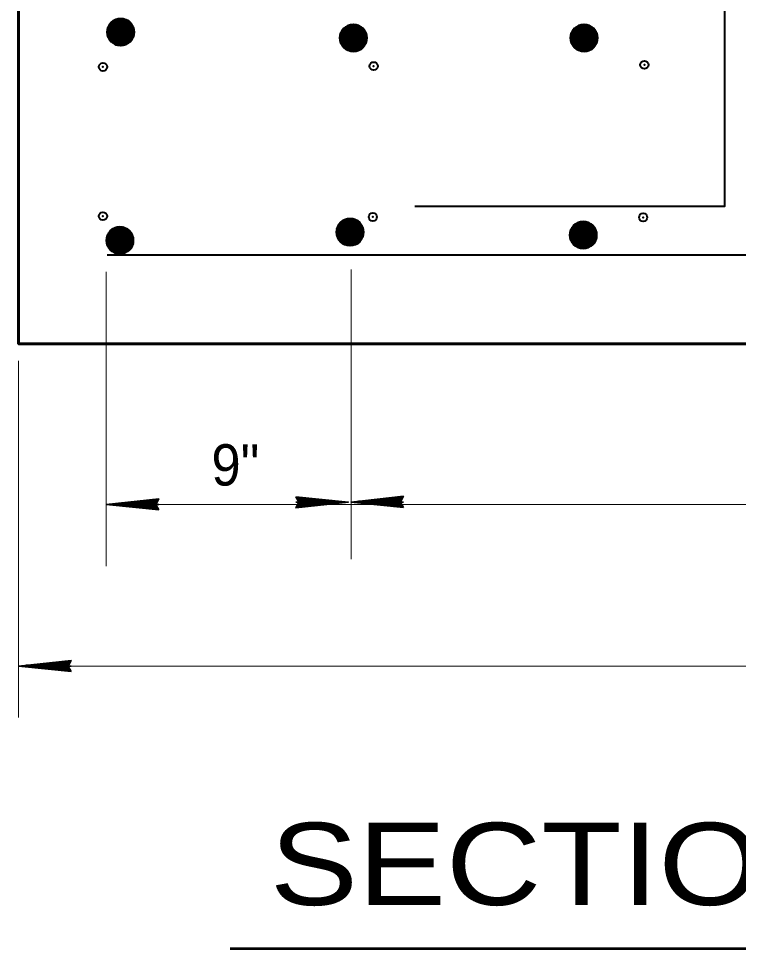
# Model space of a CAD drawing. Extents: x 14.14 to 17.34, y -1.61 to 0.38.
# Drawn here: x 15.6814 to 15.8265, y -0.6192 to -0.4318 of the extents above; entities that cross this region are included whole.
import ezdxf
from ezdxf.enums import TextEntityAlignment as Align

# ---------------------------------------------------------------- set-up
doc = ezdxf.new("R2010")
doc.units = 0
doc.header["$LTSCALE"] = 0.0033
doc.header["$PDMODE"] = 32
doc.header["$PDSIZE"] = 0.00165
doc.layers.add('1', color=7, linetype='Continuous', lineweight=40)

msp = doc.modelspace()

# ---------------------------------------------------------------- linework, layer by layer
at = {"layer": '1'}
for p, q in [((15.699917, -0.432917), (15.7045, -0.435083)), ((15.70025, -0.432917), (15.704167, -0.433583)), ((15.70025, -0.433083), (15.704167, -0.433833)), ((15.700333, -0.432583), (15.704167, -0.43325)), ((15.70225, -0.433417), (15.703583, -0.432417)), ((15.704333, -0.43325), (15.703083, -0.432083)), ((15.699917, -0.43475), (15.703833, -0.4355)), ((15.7, -0.434333), (15.703833, -0.435083)), ((15.7, -0.4345), (15.703833, -0.43525)), ((15.700083, -0.433917), (15.703917, -0.434583)), ((15.700083, -0.434083), (15.703917, -0.434833)), ((15.700167, -0.433333), (15.704083, -0.434083)), ((15.700167, -0.4335), (15.704083, -0.43425)), ((15.700167, -0.43375), (15.704, -0.4345)), ((15.746833, -0.434083), (15.751417, -0.43625)), ((15.747083, -0.4345), (15.751, -0.43525)), ((15.747083, -0.434667), (15.751, -0.435417)), ((15.747083, -0.434917), (15.750917, -0.435667)), ((15.747167, -0.434083), (15.751083, -0.43475)), ((15.747167, -0.43425), (15.751083, -0.435)), ((15.74725, -0.43375), (15.751083, -0.434417)), ((15.749167, -0.434583), (15.7505, -0.433583)), ((15.75125, -0.434417), (15.75, -0.43325)), ((15.793333, -0.434083), (15.797917, -0.43625)), ((15.793583, -0.4345), (15.7975, -0.43525)), ((15.793583, -0.434667), (15.7975, -0.435417)), ((15.793583, -0.434917), (15.797417, -0.435667)), ((15.793667, -0.434083), (15.797583, -0.43475)), ((15.793667, -0.43425), (15.797583, -0.435)), ((15.79375, -0.43375), (15.797583, -0.434417)), ((15.795667, -0.434583), (15.797, -0.433583)), ((15.79775, -0.434417), (15.7965, -0.43325)), ((15.69975, -0.435667), (15.703583, -0.436417)), ((15.69975, -0.435833), (15.703583, -0.436583)), ((15.699833, -0.435167), (15.70375, -0.435917)), ((15.699833, -0.435333), (15.703667, -0.436083)), ((15.699833, -0.435583), (15.703667, -0.43625)), ((15.704083, -0.436083), (15.700333, -0.4365)), ((15.746667, -0.436833), (15.7505, -0.437583)), ((15.74675, -0.436333), (15.750667, -0.437083)), ((15.74675, -0.4365), (15.750583, -0.43725)), ((15.74675, -0.43675), (15.750583, -0.437417)), ((15.746833, -0.435917), (15.75075, -0.436667)), ((15.746917, -0.4355), (15.75075, -0.43625)), ((15.746917, -0.435667), (15.75075, -0.436417)), ((15.747, -0.435083), (15.750833, -0.43575)), ((15.747, -0.43525), (15.750833, -0.436)), ((15.793167, -0.436833), (15.797, -0.437583)), ((15.79325, -0.436333), (15.797167, -0.437083)), ((15.79325, -0.4365), (15.797083, -0.43725)), ((15.79325, -0.43675), (15.797083, -0.437417)), ((15.793333, -0.435917), (15.79725, -0.436667)), ((15.793417, -0.4355), (15.79725, -0.43625)), ((15.793417, -0.435667), (15.79725, -0.436417)), ((15.7935, -0.435083), (15.797333, -0.43575)), ((15.7935, -0.43525), (15.797333, -0.436)), ((15.746667, -0.437), (15.7505, -0.43775)), ((15.751, -0.43725), (15.74725, -0.437667)), ((15.793167, -0.437), (15.797, -0.43775)), ((15.7975, -0.43725), (15.79375, -0.437667)), ((15.750583, -0.473583), (15.749333, -0.472417)), ((15.704167, -0.47525), (15.702917, -0.474083)), ((15.746167, -0.47325), (15.75075, -0.475417)), ((15.746333, -0.47425), (15.750167, -0.474917)), ((15.746417, -0.473667), (15.750333, -0.474417)), ((15.746417, -0.473833), (15.750333, -0.474583)), ((15.746417, -0.474083), (15.75025, -0.474833)), ((15.7465, -0.47325), (15.750417, -0.473917)), ((15.7465, -0.473417), (15.750417, -0.474167)), ((15.746583, -0.472917), (15.750417, -0.473583)), ((15.7485, -0.47375), (15.749833, -0.47275)), ((15.793167, -0.473833), (15.79775, -0.476)), ((15.793417, -0.47425), (15.797333, -0.475)), ((15.7935, -0.473833), (15.797417, -0.4745)), ((15.7935, -0.474), (15.797417, -0.47475)), ((15.793583, -0.4735), (15.797417, -0.474167)), ((15.7955, -0.474333), (15.796833, -0.473333)), ((15.797583, -0.474167), (15.796333, -0.473)), ((15.69975, -0.474917), (15.704333, -0.477083)), ((15.699917, -0.475917), (15.70375, -0.476583)), ((15.699917, -0.476083), (15.70375, -0.476833)), ((15.7, -0.475333), (15.703917, -0.476083)), ((15.7, -0.4755), (15.703917, -0.47625)), ((15.7, -0.47575), (15.703833, -0.4765)), ((15.700083, -0.474917), (15.704, -0.475583)), ((15.700083, -0.475083), (15.704, -0.475833)), ((15.700167, -0.474583), (15.704, -0.47525)), ((15.702083, -0.475417), (15.703417, -0.474417)), ((15.746, -0.476), (15.749833, -0.47675)), ((15.746, -0.476167), (15.749833, -0.476917)), ((15.746083, -0.4755), (15.75, -0.47625)), ((15.746083, -0.475667), (15.749917, -0.476417)), ((15.746083, -0.475917), (15.749917, -0.476583)), ((15.746167, -0.475083), (15.750083, -0.475833)), ((15.74625, -0.474667), (15.750083, -0.475417)), ((15.74625, -0.474833), (15.750083, -0.475583)), ((15.746333, -0.474417), (15.750167, -0.475167)), ((15.793083, -0.476083), (15.797, -0.476833)), ((15.793167, -0.475667), (15.797083, -0.476417)), ((15.79325, -0.47525), (15.797083, -0.476)), ((15.79325, -0.475417), (15.797083, -0.476167)), ((15.793333, -0.474833), (15.797167, -0.4755)), ((15.793333, -0.475), (15.797167, -0.47575)), ((15.793417, -0.474417), (15.797333, -0.475167)), ((15.793417, -0.474667), (15.79725, -0.475417)), ((15.699583, -0.477667), (15.703417, -0.478417)), ((15.699583, -0.477833), (15.703417, -0.478583)), ((15.699667, -0.477167), (15.703583, -0.477917)), ((15.699667, -0.477333), (15.7035, -0.478083)), ((15.699667, -0.477583), (15.7035, -0.47825)), ((15.69975, -0.47675), (15.703667, -0.4775)), ((15.699833, -0.476333), (15.703667, -0.477083)), ((15.699833, -0.4765), (15.703667, -0.47725)), ((15.703917, -0.478083), (15.700167, -0.4785)), ((15.750333, -0.476417), (15.746583, -0.476833)), ((15.793, -0.476583), (15.796833, -0.477333)), ((15.793, -0.47675), (15.796833, -0.4775)), ((15.793083, -0.47625), (15.796917, -0.477)), ((15.793083, -0.4765), (15.796917, -0.477167)), ((15.797333, -0.477), (15.793583, -0.477417)), ((15.69925, -0.479417), (16.07975, -0.479417))]:
    msp.add_line(p, q, dxfattribs=at)
at = {"layer": '1', "lineweight": 60}
for p, q in [((15.700167, -0.432917), (15.7, -0.435833)), ((15.700417, -0.432917), (15.700167, -0.435833)), ((15.700583, -0.432917), (15.700417, -0.435917)), ((15.70075, -0.432917), (15.7005, -0.435917)), ((15.700917, -0.432917), (15.70075, -0.435917)), ((15.701167, -0.432917), (15.701, -0.435917)), ((15.701417, -0.432917), (15.701167, -0.435917)), ((15.7015, -0.433), (15.701333, -0.435917)), ((15.701667, -0.433), (15.7015, -0.435917)), ((15.701833, -0.433), (15.701667, -0.435917)), ((15.702083, -0.433), (15.701833, -0.435917)), ((15.70225, -0.433), (15.702083, -0.435917)), ((15.7025, -0.433083), (15.70225, -0.436)), ((15.70275, -0.433083), (15.7025, -0.436)), ((15.702917, -0.433083), (15.70275, -0.436)), ((15.703, -0.433083), (15.702833, -0.436)), ((15.703167, -0.433083), (15.703, -0.436)), ((15.70325, -0.433083), (15.703083, -0.436)), ((15.7035, -0.433167), (15.70325, -0.436083)), ((15.703667, -0.433167), (15.7035, -0.436083)), ((15.703833, -0.433167), (15.703583, -0.436083)), ((15.704, -0.433167), (15.703833, -0.436083)), ((15.70425, -0.433167), (15.704083, -0.436083)), ((15.7045, -0.435083), (15.704333, -0.43325)), ((15.747083, -0.434083), (15.746917, -0.437)), ((15.747333, -0.434083), (15.747083, -0.437)), ((15.7475, -0.434083), (15.747333, -0.437083)), ((15.747667, -0.434083), (15.747417, -0.437083)), ((15.747833, -0.434083), (15.747667, -0.437083)), ((15.748083, -0.434083), (15.747917, -0.437083)), ((15.748333, -0.434083), (15.748083, -0.437083)), ((15.748417, -0.434167), (15.74825, -0.437083)), ((15.748583, -0.434167), (15.748417, -0.437083)), ((15.74875, -0.434167), (15.748583, -0.437083)), ((15.749, -0.434167), (15.74875, -0.437083)), ((15.749167, -0.434167), (15.749, -0.437083)), ((15.749417, -0.43425), (15.749167, -0.437167)), ((15.749667, -0.43425), (15.749417, -0.437167)), ((15.749833, -0.43425), (15.749667, -0.437167)), ((15.749917, -0.43425), (15.74975, -0.437167)), ((15.750083, -0.43425), (15.749917, -0.437167)), ((15.750167, -0.43425), (15.75, -0.437167)), ((15.750417, -0.434333), (15.750167, -0.43725)), ((15.750583, -0.434333), (15.750417, -0.43725)), ((15.75075, -0.434333), (15.7505, -0.43725)), ((15.750917, -0.434333), (15.75075, -0.43725)), ((15.751167, -0.434333), (15.751, -0.43725)), ((15.751417, -0.43625), (15.75125, -0.434417)), ((15.793583, -0.434083), (15.793417, -0.437)), ((15.793833, -0.434083), (15.793583, -0.437)), ((15.794, -0.434083), (15.793833, -0.437083)), ((15.794167, -0.434083), (15.793917, -0.437083)), ((15.794333, -0.434083), (15.794167, -0.437083)), ((15.794583, -0.434083), (15.794417, -0.437083)), ((15.794833, -0.434083), (15.794583, -0.437083)), ((15.794917, -0.434167), (15.79475, -0.437083)), ((15.795083, -0.434167), (15.794917, -0.437083)), ((15.79525, -0.434167), (15.795083, -0.437083)), ((15.7955, -0.434167), (15.79525, -0.437083)), ((15.795667, -0.434167), (15.7955, -0.437083)), ((15.795917, -0.43425), (15.795667, -0.437167)), ((15.796167, -0.43425), (15.795917, -0.437167)), ((15.796333, -0.43425), (15.796167, -0.437167)), ((15.796417, -0.43425), (15.79625, -0.437167)), ((15.796583, -0.43425), (15.796417, -0.437167)), ((15.796667, -0.43425), (15.7965, -0.437167)), ((15.796917, -0.434333), (15.796667, -0.43725)), ((15.797083, -0.434333), (15.796917, -0.43725)), ((15.79725, -0.434333), (15.797, -0.43725)), ((15.797417, -0.434333), (15.79725, -0.43725)), ((15.797667, -0.434333), (15.7975, -0.43725)), ((15.797917, -0.43625), (15.79775, -0.434417)), ((15.7045, -0.435083), (15.69975, -0.435833)), ((15.751417, -0.43625), (15.746667, -0.437)), ((15.797917, -0.43625), (15.793167, -0.437)), ((15.746417, -0.47325), (15.74625, -0.476167)), ((15.746667, -0.47325), (15.746417, -0.476167)), ((15.746833, -0.47325), (15.746667, -0.47625)), ((15.747, -0.47325), (15.74675, -0.47625)), ((15.747167, -0.47325), (15.747, -0.47625)), ((15.747417, -0.47325), (15.74725, -0.47625)), ((15.747667, -0.47325), (15.747417, -0.47625)), ((15.74775, -0.473333), (15.747583, -0.47625)), ((15.747917, -0.473333), (15.74775, -0.47625)), ((15.748083, -0.473333), (15.747917, -0.47625)), ((15.748333, -0.473333), (15.748083, -0.47625)), ((15.7485, -0.473333), (15.748333, -0.47625)), ((15.74875, -0.473417), (15.7485, -0.476333)), ((15.749, -0.473417), (15.74875, -0.476333)), ((15.749167, -0.473417), (15.749, -0.476333)), ((15.74925, -0.473417), (15.749083, -0.476333)), ((15.749417, -0.473417), (15.74925, -0.476333)), ((15.7495, -0.473417), (15.749333, -0.476333)), ((15.74975, -0.4735), (15.7495, -0.476417)), ((15.749917, -0.4735), (15.74975, -0.476417)), ((15.750083, -0.4735), (15.749833, -0.476417)), ((15.75025, -0.4735), (15.750083, -0.476417)), ((15.7505, -0.4735), (15.750333, -0.476417)), ((15.75075, -0.475417), (15.750583, -0.473583)), ((15.793417, -0.473833), (15.79325, -0.47675)), ((15.793667, -0.473833), (15.793417, -0.47675)), ((15.793833, -0.473833), (15.793667, -0.476833)), ((15.794, -0.473833), (15.79375, -0.476833)), ((15.794167, -0.473833), (15.794, -0.476833)), ((15.794417, -0.473833), (15.79425, -0.476833)), ((15.794667, -0.473833), (15.794417, -0.476833)), ((15.79475, -0.473917), (15.794583, -0.476833)), ((15.794917, -0.473917), (15.79475, -0.476833)), ((15.795083, -0.473917), (15.794917, -0.476833)), ((15.795333, -0.473917), (15.795083, -0.476833)), ((15.7955, -0.473917), (15.795333, -0.476833)), ((15.79575, -0.474), (15.7955, -0.476917)), ((15.796, -0.474), (15.79575, -0.476917)), ((15.796167, -0.474), (15.796, -0.476917)), ((15.79625, -0.474), (15.796083, -0.476917)), ((15.796417, -0.474), (15.79625, -0.476917)), ((15.7965, -0.474), (15.796333, -0.476917)), ((15.79675, -0.474083), (15.7965, -0.477)), ((15.796917, -0.474083), (15.79675, -0.477)), ((15.797083, -0.474083), (15.796833, -0.477)), ((15.79725, -0.474083), (15.797083, -0.477)), ((15.7975, -0.474083), (15.797333, -0.477)), ((15.79775, -0.476), (15.797583, -0.474167)), ((15.7, -0.474917), (15.699833, -0.477833)), ((15.70025, -0.474917), (15.7, -0.477833)), ((15.700417, -0.474917), (15.70025, -0.477917)), ((15.700583, -0.474917), (15.700333, -0.477917)), ((15.70075, -0.474917), (15.700583, -0.477917)), ((15.701, -0.474917), (15.700833, -0.477917)), ((15.70125, -0.474917), (15.701, -0.477917)), ((15.701333, -0.475), (15.701167, -0.477917)), ((15.7015, -0.475), (15.701333, -0.477917)), ((15.701667, -0.475), (15.7015, -0.477917)), ((15.701917, -0.475), (15.701667, -0.477917)), ((15.702083, -0.475), (15.701917, -0.477917)), ((15.702333, -0.475083), (15.702083, -0.478)), ((15.702583, -0.475083), (15.702333, -0.478)), ((15.70275, -0.475083), (15.702583, -0.478)), ((15.702833, -0.475083), (15.702667, -0.478)), ((15.703, -0.475083), (15.702833, -0.478)), ((15.703083, -0.475083), (15.702917, -0.478)), ((15.703333, -0.475167), (15.703083, -0.478083)), ((15.7035, -0.475167), (15.703333, -0.478083)), ((15.703667, -0.475167), (15.703417, -0.478083)), ((15.703833, -0.475167), (15.703667, -0.478083)), ((15.704083, -0.475167), (15.703917, -0.478083)), ((15.704333, -0.477083), (15.704167, -0.47525)), ((15.75075, -0.475417), (15.746, -0.476167)), ((15.79775, -0.476), (15.793, -0.47675)), ((15.704333, -0.477083), (15.699583, -0.477833))]:
    msp.add_line(p, q, dxfattribs=at)
at = {"layer": '1', "lineweight": 13}
for p, q in [((15.699083, -0.482833), (15.699083, -0.542167)), ((15.7485, -0.482333), (15.7485, -0.54075)), ((15.681417, -0.50075), (15.681417, -0.572667)), ((15.699083, -0.52975), (16.080083, -0.52975)), ((15.681417, -0.562333), (16.09775, -0.562333))]:
    msp.add_line(p, q, dxfattribs=at)
at = {"layer": '1', "lineweight": 35}
for p, q in [((15.709417, -0.528667), (15.702083, -0.5295)), ((15.737583, -0.52825), (15.745417, -0.529167)), ((15.737583, -0.52825), (15.745417, -0.529167)), ((15.737583, -0.528333), (15.745417, -0.529167)), ((15.737583, -0.528417), (15.745417, -0.52925)), ((15.737583, -0.528417), (15.745417, -0.529417)), ((15.75875, -0.528167), (15.751417, -0.529)), ((15.75875, -0.528333), (15.751417, -0.529083)), ((15.75875, -0.528417), (15.751417, -0.52925)), ((15.758833, -0.528583), (15.7515, -0.529333)), ((15.709667, -0.52975), (15.699083, -0.52975)), ((15.709417, -0.530583), (15.701583, -0.529583)), ((15.709417, -0.530583), (15.701583, -0.52975)), ((15.709417, -0.53075), (15.701583, -0.529833)), ((15.709417, -0.53075), (15.701583, -0.529833)), ((15.709417, -0.530667), (15.701583, -0.529833)), ((15.709417, -0.528833), (15.702083, -0.529583)), ((15.709417, -0.528917), (15.702083, -0.52975)), ((15.7095, -0.529083), (15.702167, -0.529833)), ((15.737333, -0.52925), (15.747917, -0.52925)), ((15.7375, -0.529917), (15.744833, -0.529167)), ((15.737583, -0.530083), (15.744917, -0.52925)), ((15.737583, -0.530167), (15.744917, -0.529417)), ((15.737583, -0.530333), (15.744917, -0.5295)), ((15.759, -0.52925), (15.748417, -0.52925)), ((15.75875, -0.530083), (15.750917, -0.529083)), ((15.75875, -0.530083), (15.750917, -0.52925)), ((15.75875, -0.53025), (15.750917, -0.529333)), ((15.75875, -0.53025), (15.750917, -0.529333)), ((15.75875, -0.530167), (15.750917, -0.529333)), ((15.692, -0.562333), (15.681417, -0.562333)), ((15.69175, -0.563167), (15.683917, -0.562167)), ((15.69175, -0.563167), (15.683917, -0.562333)), ((15.69175, -0.563333), (15.683917, -0.562417)), ((15.69175, -0.563333), (15.683917, -0.562417)), ((15.69175, -0.56325), (15.683917, -0.562417)), ((15.69175, -0.56125), (15.684417, -0.562083)), ((15.69175, -0.561417), (15.684417, -0.562167)), ((15.69175, -0.5615), (15.684417, -0.562333)), ((15.691833, -0.561667), (15.6845, -0.562417))]:
    msp.add_line(p, q, dxfattribs=at)
at = {"layer": '1', "lineweight": 53}
msp.add_line((15.724083, -0.61925), (16.06175, -0.61925), dxfattribs=at)
at = {"layer": '1'}
for points in [[(15.761333, -0.469583), (15.823833, -0.469583), (15.823833, -0.357417)], [(15.69975, -0.435833), (15.701833, -0.437083), (15.703583, -0.436583), (15.7045, -0.435083)], [(15.746667, -0.437), (15.74875, -0.43825), (15.7505, -0.43775), (15.751417, -0.43625)], [(15.793167, -0.437), (15.79525, -0.43825), (15.797, -0.43775), (15.797917, -0.43625)], [(15.746, -0.476167), (15.748083, -0.477417), (15.749833, -0.476917), (15.75075, -0.475417)], [(15.793, -0.47675), (15.795083, -0.478), (15.796833, -0.4775), (15.79775, -0.476)], [(15.699583, -0.477833), (15.701667, -0.479083), (15.703417, -0.478583), (15.704333, -0.477083)]]:
    msp.add_lwpolyline(points, dxfattribs=at)
at = {"layer": '1', "lineweight": 60}
for points in [[(15.681417, -0.414), (15.681417, -0.497333), (16.098083, -0.497333), (16.098083, -0.414)], [(15.699333, -0.434583), (15.7045, -0.433917), (15.699917, -0.432917)], [(15.703583, -0.436583), (15.703583, -0.432417), (15.701917, -0.437083), (15.702417, -0.431917), (15.700333, -0.4365), (15.701083, -0.432), (15.702667, -0.437), (15.6995, -0.433667), (15.704333, -0.43325), (15.701083, -0.436917), (15.703083, -0.432083), (15.699917, -0.432917), (15.69975, -0.435833)], [(15.700333, -0.4365), (15.701833, -0.43425), (15.699667, -0.433333), (15.701667, -0.431917), (15.701833, -0.434167), (15.7035, -0.4365), (15.6995, -0.434167), (15.70225, -0.433417)], [(15.703083, -0.432083), (15.701833, -0.43425), (15.704083, -0.436083)], [(15.7505, -0.43775), (15.7505, -0.433583), (15.748833, -0.43825), (15.749333, -0.433083), (15.74725, -0.437667), (15.748, -0.433167), (15.749583, -0.438167), (15.746417, -0.434833), (15.75125, -0.434417), (15.748, -0.438083), (15.75, -0.43325), (15.746833, -0.434083), (15.746667, -0.437)], [(15.74725, -0.437667), (15.74875, -0.435417), (15.746583, -0.4345), (15.748583, -0.433083), (15.74875, -0.435333), (15.750417, -0.437667), (15.746417, -0.435333), (15.749167, -0.434583)], [(15.797, -0.43775), (15.797, -0.433583), (15.795333, -0.43825), (15.795833, -0.433083), (15.79375, -0.437667), (15.7945, -0.433167), (15.796083, -0.438167), (15.792917, -0.434833), (15.79775, -0.434417), (15.7945, -0.438083), (15.7965, -0.43325), (15.793333, -0.434083), (15.793167, -0.437)], [(15.79375, -0.437667), (15.79525, -0.435417), (15.793083, -0.4345), (15.795083, -0.433083), (15.79525, -0.435333), (15.796917, -0.437667), (15.792917, -0.435333), (15.795667, -0.434583)], [(15.74625, -0.43575), (15.751417, -0.435083), (15.746833, -0.434083)], [(15.75, -0.43325), (15.74875, -0.435417), (15.751, -0.43725)], [(15.79275, -0.43575), (15.797917, -0.435083), (15.793333, -0.434083)], [(15.7965, -0.43325), (15.79525, -0.435417), (15.7975, -0.43725)], [(15.749833, -0.476917), (15.749833, -0.47275), (15.748167, -0.477417), (15.748667, -0.47225), (15.746583, -0.476833), (15.747333, -0.472333), (15.748917, -0.477333), (15.74575, -0.474), (15.750583, -0.473583), (15.747333, -0.47725), (15.749333, -0.472417), (15.746167, -0.47325), (15.746, -0.476167)], [(15.746583, -0.476833), (15.748083, -0.474583), (15.745917, -0.473667), (15.747917, -0.47225), (15.748083, -0.4745), (15.74975, -0.476833), (15.74575, -0.4745), (15.7485, -0.47375)], [(15.749333, -0.472417), (15.748083, -0.474583), (15.750333, -0.476417)], [(15.703417, -0.478583), (15.703417, -0.474417), (15.70175, -0.479083), (15.70225, -0.473917), (15.700167, -0.4785), (15.700917, -0.474), (15.7025, -0.479), (15.699333, -0.475667), (15.704167, -0.47525), (15.700917, -0.478917), (15.702917, -0.474083), (15.69975, -0.474917), (15.699583, -0.477833)], [(15.700167, -0.4785), (15.701667, -0.47625), (15.6995, -0.475333), (15.7015, -0.473917), (15.701667, -0.476167), (15.703333, -0.4785), (15.699333, -0.476167), (15.702083, -0.475417)], [(15.702917, -0.474083), (15.701667, -0.47625), (15.703917, -0.478083)], [(15.745583, -0.474917), (15.75075, -0.47425), (15.746167, -0.47325)], [(15.792583, -0.4755), (15.79775, -0.474833), (15.793167, -0.473833)], [(15.796833, -0.4775), (15.796833, -0.473333), (15.795167, -0.478), (15.795667, -0.472833), (15.793583, -0.477417), (15.794333, -0.472917), (15.795917, -0.477917), (15.79275, -0.474583), (15.797583, -0.474167), (15.794333, -0.477833), (15.796333, -0.473), (15.793167, -0.473833), (15.793, -0.47675)], [(15.793583, -0.477417), (15.795083, -0.475167), (15.792917, -0.47425), (15.794917, -0.472833), (15.795083, -0.475083), (15.79675, -0.477417), (15.79275, -0.475083), (15.7955, -0.474333)], [(15.796333, -0.473), (15.795083, -0.475167), (15.797333, -0.477)], [(15.699167, -0.476583), (15.704333, -0.475917), (15.69975, -0.474917)]]:
    msp.add_lwpolyline(points, dxfattribs=at)
at = {"layer": '1', "lineweight": 35}
for points in [[(15.709667, -0.530833), (15.699083, -0.52975), (15.709667, -0.528583), (15.709083, -0.52975)], [(15.737333, -0.528167), (15.747917, -0.52925), (15.737333, -0.530417), (15.737917, -0.52925)], [(15.759, -0.530333), (15.748417, -0.52925), (15.759, -0.528083), (15.758417, -0.52925)], [(15.75825, -0.529333), (15.753583, -0.529417), (15.753583, -0.529333), (15.7545, -0.529333), (15.75825, -0.529417), (15.75525, -0.5295), (15.758417, -0.529583), (15.756167, -0.529667), (15.758417, -0.52975), (15.754917, -0.5295), (15.75025, -0.529333), (15.751167, -0.529083), (15.749917, -0.529083), (15.75825, -0.529083), (15.755833, -0.528917), (15.758417, -0.528917), (15.753083, -0.529333), (15.758417, -0.528667)], [(15.708917, -0.529833), (15.70425, -0.529917), (15.70425, -0.529833), (15.705167, -0.529833), (15.708917, -0.529917), (15.705917, -0.53), (15.709083, -0.530083), (15.706833, -0.530167), (15.709083, -0.53025), (15.705583, -0.53), (15.700917, -0.529833), (15.701833, -0.529583), (15.700583, -0.529583), (15.708917, -0.529583), (15.7065, -0.529417), (15.709083, -0.529417), (15.70375, -0.529833), (15.709083, -0.529167)], [(15.738083, -0.529167), (15.74275, -0.529083), (15.74275, -0.529167), (15.741833, -0.529167), (15.738083, -0.529083), (15.741083, -0.529), (15.737917, -0.528917), (15.740167, -0.528833), (15.737917, -0.52875), (15.741417, -0.529), (15.746083, -0.529167), (15.745167, -0.529417), (15.746417, -0.529417), (15.738083, -0.529417), (15.7405, -0.529583), (15.737917, -0.529583), (15.74325, -0.529167), (15.737917, -0.529833)], [(15.692, -0.563417), (15.681417, -0.562333), (15.692, -0.561167), (15.691417, -0.562333)], [(15.69125, -0.562417), (15.686583, -0.5625), (15.686583, -0.562417), (15.6875, -0.562417), (15.69125, -0.5625), (15.68825, -0.562583), (15.691417, -0.562667), (15.689167, -0.56275), (15.691417, -0.562833), (15.687917, -0.562583), (15.68325, -0.562417), (15.684167, -0.562167), (15.682917, -0.562167), (15.69125, -0.562167), (15.688833, -0.562), (15.691417, -0.562), (15.686083, -0.562417), (15.691417, -0.56175)]]:
    msp.add_lwpolyline(points, close=True, dxfattribs=at)
for points in [[(15.738083, -0.529167), (15.737667, -0.528417), (15.737917, -0.528667), (15.738083, -0.529), (15.738333, -0.528917), (15.738167, -0.528583), (15.738, -0.529333), (15.737833, -0.529833), (15.737583, -0.53025)], [(15.75825, -0.529333), (15.758667, -0.530083), (15.758417, -0.529833), (15.75825, -0.5295), (15.758, -0.529583), (15.758167, -0.529917), (15.758333, -0.529167), (15.7585, -0.528667), (15.75875, -0.52825)], [(15.708917, -0.529833), (15.709333, -0.530583), (15.709083, -0.530333), (15.708917, -0.53), (15.708667, -0.530083), (15.708833, -0.530417), (15.709, -0.529667), (15.709167, -0.529167), (15.709417, -0.52875)], [(15.69125, -0.562417), (15.691667, -0.563167), (15.691417, -0.562917), (15.69125, -0.562583), (15.691, -0.562667), (15.691167, -0.563), (15.691333, -0.56225), (15.6915, -0.56175), (15.69175, -0.561333)]]:
    msp.add_lwpolyline(points, dxfattribs=at)
at = {"layer": '1', "lineweight": 60}
for centre in [(15.702, -0.434483), (15.748917, -0.43565), (15.795417, -0.43565), (15.74825, -0.474817), (15.701833, -0.476483), (15.79525, -0.4754)]:
    msp.add_circle(centre, 0.00264, dxfattribs=at)
at = {"layer": '1'}
for p in [(15.701417, -0.436333), (15.748417, -0.43625), (15.7955, -0.436083), (15.753, -0.441333), (15.807583, -0.441083), (15.698417, -0.4415), (15.698417, -0.471583), (15.752833, -0.47175), (15.807333, -0.471833), (15.701417, -0.476167), (15.748333, -0.476167), (15.795333, -0.476167)]:
    msp.add_point(p, dxfattribs=at)

# ---------------------------------------------------------------- texts
at = {"layer": '1', "width": 0.95}
msp.add_text('9"', height=0.008334, dxfattribs=at).set_placement((15.725125, -0.525917), align=Align.CENTER)
at = {"layer": '1', "width": 1.2}
msp.add_text("SECTION 'B-B' (RANGE II)", height=0.01658, dxfattribs=at).set_placement((15.732083, -0.6105))

doc.saveas('drawing.dxf')
